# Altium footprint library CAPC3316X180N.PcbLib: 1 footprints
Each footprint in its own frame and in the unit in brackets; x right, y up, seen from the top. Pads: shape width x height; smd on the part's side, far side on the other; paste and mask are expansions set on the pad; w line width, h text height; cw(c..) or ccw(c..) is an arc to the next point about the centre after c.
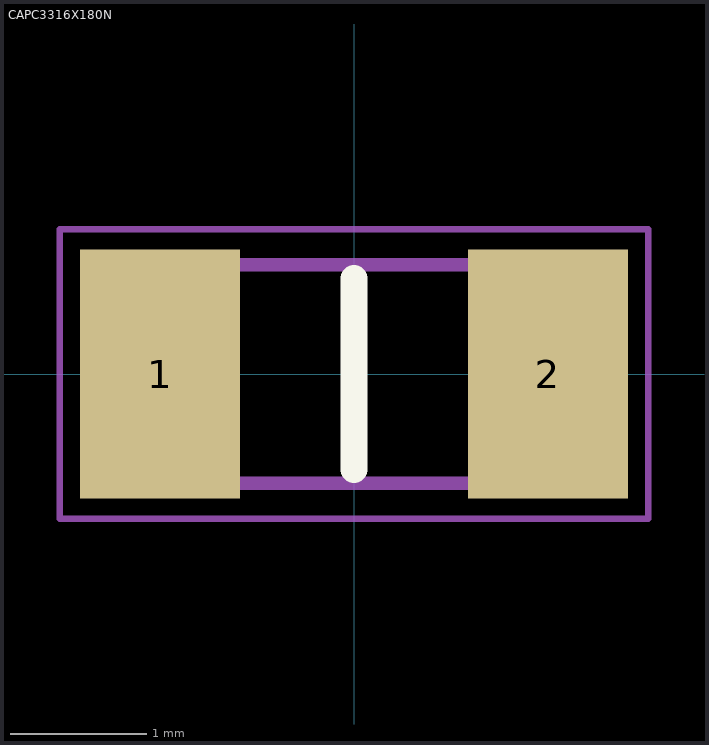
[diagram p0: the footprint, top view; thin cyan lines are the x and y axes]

## CAPC3316X180N [mm]
pads (2):
  rect 1.17x1.82 smd: 1(-1.42,0) 2(1.42,0)
Top Overlay:
  lines w0.2: 0,-0.7 0,0.7
Mechanical 15:
  lines w0.1: -1.65,-0.8 1.65,-0.8 1.65,0.8 -1.65,0.8 -1.65,-0.8
Mechanical 20:
  lines w0.05: -2.155,-1.06 2.155,-1.06 2.155,1.06 -2.155,1.06 -2.155,-1.06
